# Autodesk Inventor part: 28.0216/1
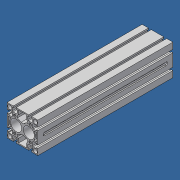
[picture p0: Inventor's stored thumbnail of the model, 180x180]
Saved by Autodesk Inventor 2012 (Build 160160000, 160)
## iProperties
Created: 2011-05
Part Number: 28.0216/1
Material: Aluminum-6061
Description: L = TRAVEL + 3.543" MILL TO 28.0216/1
Document SubType Name: Modeling
Designer: Administrator
Stock Number: 20.1019 PROFILE 90X90S
Density: 2.71 g/cm^3
Vendor: F
Author: Administrator
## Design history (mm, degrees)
sketch "Sketch1"
  geometry: L1 (-31.7, -15.7)-(-40.5, -15.7) reference; L2 (-40.5, -15.7)-(-40.5, -18.25) reference; L3 (-40.5, -18.25)-(-45, -18.25) reference; L4 (-45, -18.25)-(-45, 18.25) reference; L5 (-45, 18.25)-(-40.5, 18.25) reference; L6 (-40.5, 18.25)-(-40.5, 15.7) reference; L7 (-40.5, 15.7)-(-31.7, 15.7) reference; L8 (-31.7, 15.7)-(-29.7, 17.7) reference; L9 (-29.7, 17.7)-(-29.7, 27.3) reference; L10 (-29.7, 27.3)-(-31.7, 29.3) reference; L11 (-31.7, 29.3)-(-40.5, 29.3) reference; L12 (-40.5, 29.3)-(-40.5, 26.75) reference; L13 (-40.5, 26.75)-(-45, 26.75) reference; L14 (-45, 26.75)-(-45, 45) reference; L15 (29.3, 31.7)-(29.3, 40.5) reference; L16 (-26.75, 45)-(-26.75, 40.5) reference; L17 (-26.75, 40.5)-(-29.3, 40.5) reference; L18 (-29.3, 40.5)-(-29.3, 31.7) reference; L19 (-29.3, 31.7)-(-27.3, 29.7) reference; L20 (-27.3, 29.7)-(-17.7, 29.7) reference; L21 (-17.7, 29.7)-(-15.7, 31.7) reference; L22 (-15.7, 31.7)-(-15.7, 40.5) reference; L23 (-15.7, 40.5)-(-18.25, 40.5) reference; L24 (-18.25, 40.5)-(-18.25, 45) reference; L25 (-18.25, 45)-(18.25, 45) reference; L26 (18.25, 45)-(18.25, 40.5) reference; L27 (18.25, 40.5)-(15.7, 40.5) reference; L28 (15.7, 40.5)-(15.7, 31.7) reference; L29 (15.7, 31.7)-(17.7, 29.7) reference; L30 (17.7, 29.7)-(27.3, 29.7) reference; L31 (27.3, 29.7)-(29.3, 31.7) reference; L32 (29.3, 40.5)-(26.75, 40.5) reference; L33 (26.75, 40.5)-(26.75, 45) reference; L34 (26.75, 45)-(45, 45) reference; L35 (45, 45)-(45, 26.75) reference; L36 (45, 26.75)-(40.5, 26.75) reference; L37 (40.5, 26.75)-(40.5, 29.3) reference; L38 (40.5, 29.3)-(31.7, 29.3) reference; L39 (31.7, 29.3)-(29.7, 27.3) reference; L40 (29.7, 27.3)-(29.7, 17.7) reference; L41 (29.7, 17.7)-(31.7, 15.7) reference; L42 (31.7, 15.7)-(40.5, 15.7) reference; L43 (40.5, 15.7)-(40.5, 18.25) reference; L44 (40.5, 18.25)-(45, 18.25) reference; L45 (45, 18.25)-(45, -18.25) reference; L46 (45, -18.25)-(40.5, -18.25) reference; L47 (40.5, -18.25)-(40.5, -15.7) reference; L48 (40.5, -15.7)-(31.7, -15.7) reference; L49 (31.7, -15.7)-(29.7, -17.7) reference; L50 (29.7, -17.7)-(29.7, -27.3) reference; L51 (29.7, -27.3)-(31.7, -29.3) reference; L52 (31.7, -29.3)-(40.5, -29.3) reference; L53 (40.5, -29.3)-(40.5, -26.75) reference; L54 (40.5, -26.75)-(45, -26.75) reference; L55 (45, -26.75)-(45, -45) reference; L56 (45, -45)-(26.75, -45) reference; L57 (26.75, -45)-(26.75, -40.5) reference; L58 (26.75, -40.5)-(29.3, -40.5) reference; L59 (29.3, -40.5)-(29.3, -31.7) reference; L60 (29.3, -31.7)-(27.3, -29.7) reference; L61 (27.3, -29.7)-(17.7, -29.7) reference; L62 (17.7, -29.7)-(15.7, -31.7) reference; L63 (15.7, -31.7)-(15.7, -40.5) reference; L64 (15.7, -40.5)-(18.25, -40.5) reference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; C1 r 3.75 at (22.5, -22.5) reference; C2 r 5.85 at (37.15, 37.15) reference; C3 r 5.85 at (-37.15, 37.15) reference; C4 r 5.85 at (-37.15, -37.15) reference; C5 r 5.85 at (37.15, -37.15) reference; C6 r 3.75 at (-22.5, 22.5) reference; C7 r 3.75 at (-22.5, -22.5) reference; C8 r 3.75 at (22.5, 22.5) reference; C9 r 16 at (18.5, 0) reference; C10 r 16 at (-18.5, 0) reference; A1 r 19 centre (18.5, 0) between (33.47, -11.7) and (33.47, 11.7) reference; A2 r 19 centre (-18.5, 0) between (-33.47, 11.7) and (-33.47, -11.7) reference
  constraints: 228 end point, 17 horizontal, 17 vertical, 12 centre point, 4 point on circle, 2 midpoint, 2 point on line, 222 other
extrude "Extrusion1" new body sketch "Sketch1" stored distance "d0" = 394.8 (computed from TRAVEL); taper "d1" = 0 deg
sketch "Sketch2"
  geometry: L1 (0, 36.5)-(0, 0) reference; L2 (394.8, 0)-(394.8, 36.5) reference; L3 (20, 23)-(374.8, 23); L4 (374.8, 13.5)-(20, 13.5); A1 r 4.75 centre (20, 18.25) between (20, 23) and (20, 13.5); A2 r 4.75 centre (374.8, 18.25) between (374.8, 13.5) and (374.8, 23); 3 further points
  constraints: 6 point on circle, 4 end point, 4 tangent, 2 centre point, 2 horizontal alignment, 2 midpoint, 2 point on line, 1 equal radius
  dimensions: "d2" = 20 distance from line of A1.centre L1 (= d3); "d3" = 20 distance from line of A2.centre L2; "d4" = 4.75 radius of A1
extrude "Extrusion2" cut sketch "Sketch2" distance "d5" = 15.875; taper "d6" = 0 deg
thread "Thread1" dims "d7" = 25.4, "d8" = 0
thread "Thread2" dims "d9" = 25.4, "d10" = 0
thread "Thread3" dims "d11" = 25.4, "d12" = 0
thread "Thread4" dims "d13" = 25.4, "d14" = 0
thread "Thread5" dims "d15" = 25.4, "d16" = 0
thread "Thread6" dims "d17" = 25.4, "d18" = 0
thread "Thread7" dims "d19" = 25.4, "d20" = 0
thread "Thread8" dims "d21" = 25.4, "d22" = 0
body "Solid1"
other parameters: "TRAVEL" = 304.8 [user parameter; used in 1 equation term]
